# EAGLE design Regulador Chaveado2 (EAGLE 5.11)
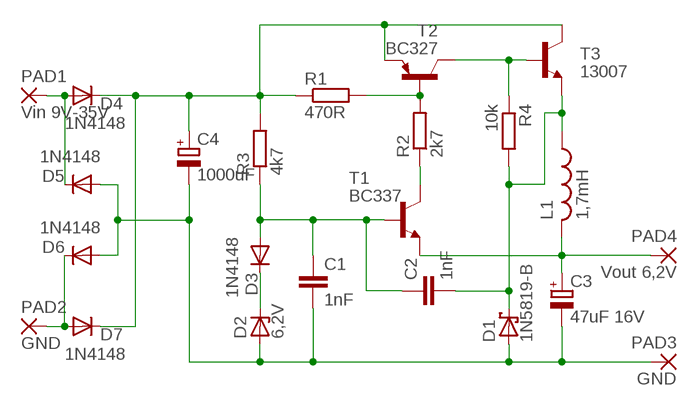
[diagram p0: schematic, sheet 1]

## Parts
C1  1nF  C-EU050-025X075  [C050-025X075]
C2  1nF  C-EU050-025X075  [C050-025X075]
C3  47uF 16V  CPOL-EUE2.5-5  [E2,5-5]
C4  1000uF  CPOL-EUE7.5-16  [E7,5-16]
D1  1N5819-B  [DO41-7.6]
D2  6,2V  ZPY  [DO41Z10]
D3  1N4148  1N4148DO35-7  [DO35-7]
D4  1N4148  1N4148DO35-7  [DO35-7]
D5  1N4148  1N4148DO35-7  [DO35-7]
D6  1N4148  1N4148DO35-7  [DO35-7]
D7  1N4148  1N4148DO35-7  [DO35-7]
L1  1,7mH  L-USL-TRAFO  [TRAFO16MM]
PAD1  Vin 9V-35V  2,54/1,0  [2,54/1,0]
PAD2  GND  2,54/1,0  [2,54/1,0]
PAD3  GND  2,54/1,0  [2,54/1,0]
PAD4  Vout 6,2V  2,54/1,0  [2,54/1,0]
R1  470R  R-EU_0207/10  [0207/10]
R2  2k7  R-EU_0207/10  [0207/10]
R3  4k7  R-EU_0207/10  [0207/10]
R4  10k  R-EU_0207/10  [0207/10]
T1  BC337  BC337-16-NPN-TO92-CBE  [TO92-CBE]
T2  BC327  MPSA63-PNP-TO92-CBE  [TO92-CBE]
T3  13007  -NPN-TO220V  [TO220V]

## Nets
N$1: C1.2 C3.- C4.- D1.A D2.A D5.A D6.A PAD3.1(P)
N$2: C3.+ L1.P$7 PAD4.1(P) T1.E
N$3: C4.+ D4.C D7.C R1.1 R3.2 T2.E T3.2(C)
N$4: D2.C D3.C
N$5: C1.1 C2.1 D3.A R3.1 T1.B
N$6: R4.1 T2.C T3.1(B)
N$7: R2.1 T1.C
N$8: D4.A D5.C PAD1.1(P)
N$9: R1.2 R2.2 T2.B
N$10: C2.2 D1.C L1.P$5 R4.2 T3.3(E)
N$11: D6.C D7.A PAD2.1(P)

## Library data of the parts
C1 C2 = resistor:C-EU: CAPACITOR, European symbol
C3 C4 = rcl:CPOL-EU: POLARIZED CAPACITOR, European symbol
D1 = diode:1N581*: 1.0A SCHOTTKY BARRIER RECTIFIER
D2 = diode:ZPY: Z DIODE
D3-D7 = diode:1N4148: DIODE
L1 = Inductors:L-US: INDUCTOR, American symbol
PAD1-PAD4 = wirepad:2,54/1,0: THROUGH-HOLE PAD
R1-R4 = resistor:R-EU_: RESISTOR, European symbol
T1 T3 = transistor:*-NPN-: NPN Transistror BF959 corrected 2008.03.06
T2 = transistor:*-PNP-: PNP Transistror

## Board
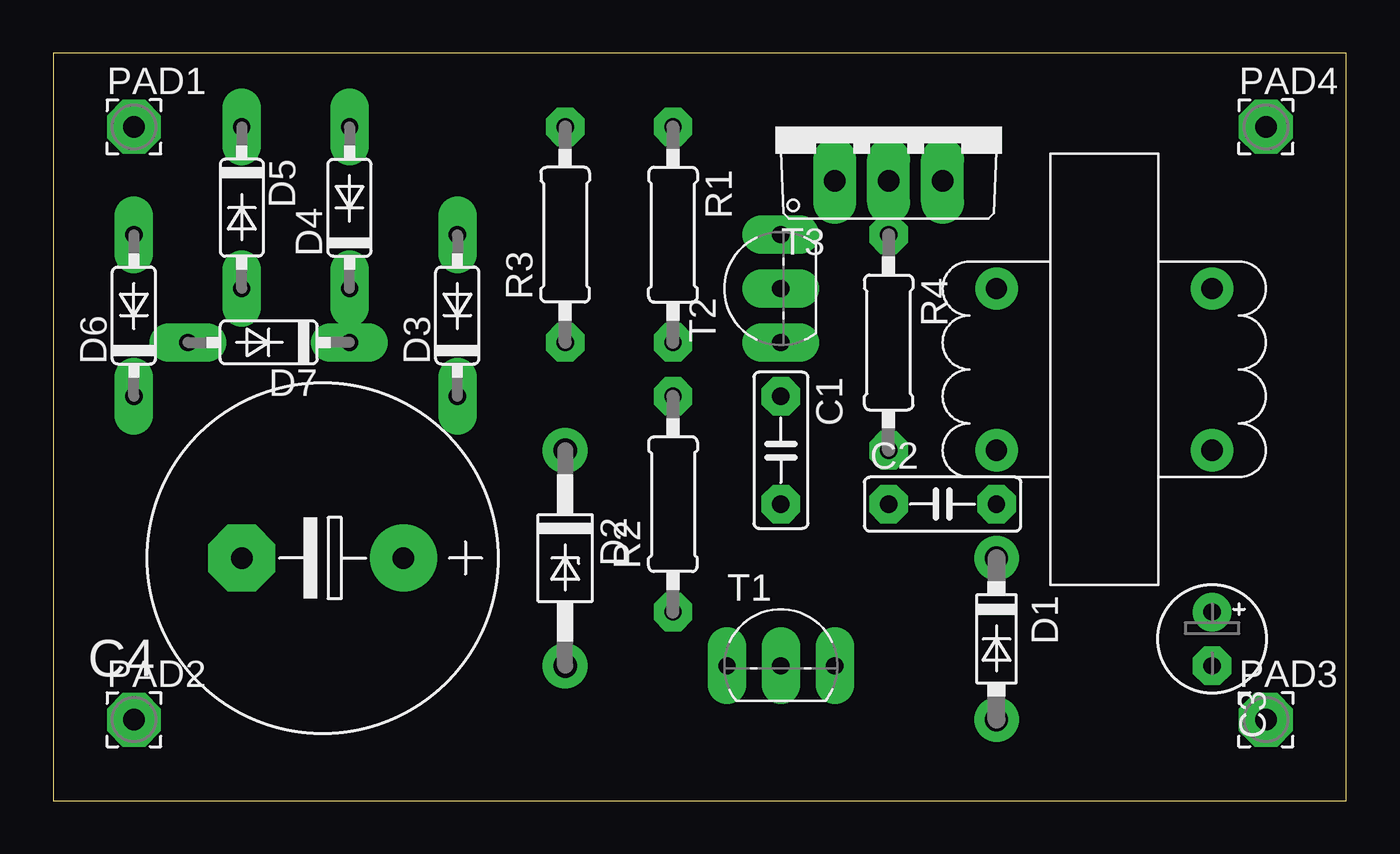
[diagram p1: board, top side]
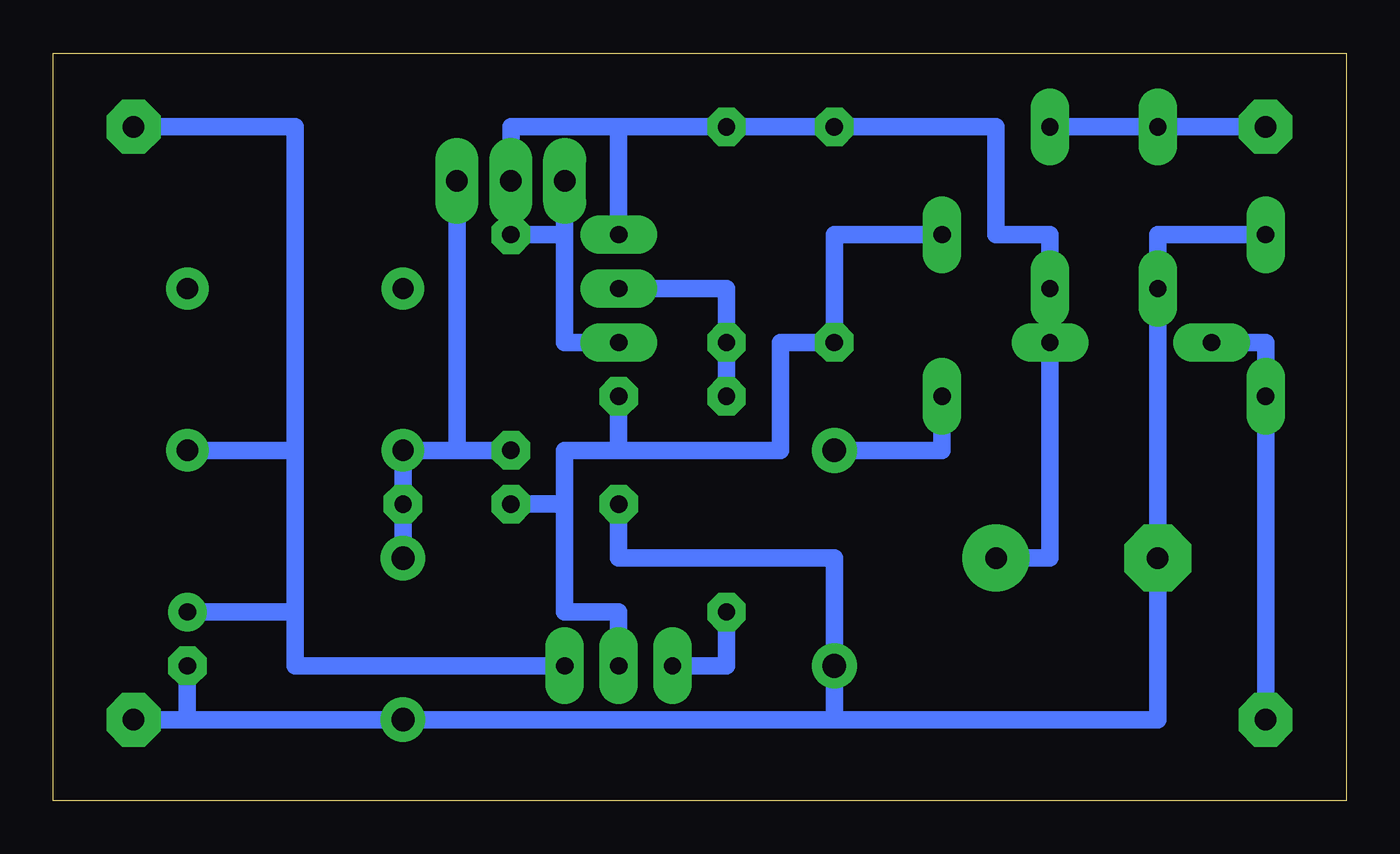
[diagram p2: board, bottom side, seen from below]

Size 60.94 x 35.23 mm. Coordinates in mm from the lower left corner, seen from the top.
Outline: 0,0 60.94,0 60.94,35.23 0,35.23 0,0
Copper layers (1*16): Top 0.035mm / dielectric 1.5mm / Bottom 0.035mm
Design rules "Manual": minimum track width 0.7mm, minimum drill 0.5mm, track to track 0.5mm, track to pad 0.5mm, pad to pad 0.5mm, via to via 1mm, smd to smd 8mil, copper to edge 40mil, drill to drill 1mm, minimum pad ring 0.5mm, minimum via ring 0.5mm, stop-mask expansion 4mil, vias tented up to drill 0mil, thermal gap 10mil

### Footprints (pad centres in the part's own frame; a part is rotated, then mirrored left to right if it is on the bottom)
C050-025X075 = drill 0.813 octagon: 1 -2.54,0; 2 2.54,0
E2,5-5 = drill 0.813 pad 1.6 round: + -1.27,0 | drill 0.813 pad 1.6 octagon: - 1.27,0
E7,5-16 = drill 1.016 pad 3.15 round: + -3.81,0 | drill 1.016 pad 3.15 octagon: - 3.81,0
DO41-7.6 = drill 1.1 pad 1.7 round: A 3.81,0; C -3.81,0
DO41Z10 = drill 1.118 round: A 5.08,0; C -5.08,0
DO35-7 = drill 0.813 long: A 3.81,0; C -3.81,0
TRAFO16MM = drill 1 round: P$5 -3.81,5.08; P$6 3.81,5.08; P$7 -3.81,-5.08; P$8 3.81,-5.08
2,54/1,0 = drill 1.016 pad 2.54 octagon: 1 0,0
0207/10 = drill 0.813 octagon: 1 -5.08,0; 2 5.08,0
TO92-CBE = drill 0.813 long: B 0,0; C -2.54,0; E 2.54,0
TO220V = drill 1.016 long: 1 -2.54,-2.54; 2 0,-2.54; 3 2.54,-2.54

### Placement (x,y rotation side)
C1  34.29,16.51 270 top
C2  41.91,13.97 0 top
C3  54.61,7.62 270 top
C4  12.7,11.43 180 top
D1  44.45,7.62 270 top
D2  24.13,11.43 270 top
D3  19.05,22.86 90 top
D4  13.97,27.94 90 top
D5  8.89,27.94 270 top
D6  3.81,22.86 90 top
D7  10.16,21.59 180 top
L1  49.53,20.32 90 top
PAD1  3.81,31.75 0 top
PAD2  3.81,3.81 0 top
PAD3  57.15,3.81 0 top
PAD4  57.15,31.75 0 top
R1  29.21,26.67 270 top
R2  29.21,13.97 90 top
R3  24.13,26.67 90 top
R4  39.37,21.59 270 top
T1  34.29,6.35 0 top
T2  34.29,24.13 90 top
T3  39.37,31.75 0 top

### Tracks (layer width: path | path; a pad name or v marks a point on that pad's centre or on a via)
N$1
  Bottom 0.813: D6.A 8.89,26.67 D5.A C4.- 8.89,3.81 24.13,3.81 | 24.13,3.81 D1.A 54.61,3.81 | 54.61,3.81 PAD3.1 | 54.61,3.81 C3.- | 24.13,3.81 D2.A 24.13,11.43 34.29,11.43 C1.2
N$2
  Bottom 0.813: 49.53,16.51 L1.P$7 | 49.53,8.89 49.53,6.35 T1.E | 49.53,8.89 49.53,16.51 | 49.53,8.89 C3.+ | PAD4.1 49.53,31.75 49.53,16.51
N$3
  Bottom 0.813: 34.29,31.75 R1.1 R3.2 16.51,31.75 16.51,26.67 13.97,26.67 D4.C D7.C 13.97,11.43 C4.+ | 34.29,31.75 39.37,31.75 T3.2 | 34.29,31.75 T2.E
N$4
  Bottom 0.813: D3.C 19.05,16.51 D2.C
N$5
  Bottom 0.813: 34.29,16.51 36.83,16.51 36.83,13.97 | 34.29,16.51 26.67,16.51 26.67,21.59 R3.1 24.13,26.67 D3.A | 36.83,13.97 36.83,8.89 34.29,8.89 T1.B | 36.83,13.97 C2.1 | 34.29,16.51 C1.1
N$6
  Bottom 0.813: 36.83,26.67 36.83,21.59 T2.C | 36.83,26.67 T3.1 | 36.83,26.67 R4.1
N$7
  Bottom 0.813: R2.1 29.21,6.35 T1.C
N$8
  Bottom 0.813: PAD1.1 D5.C D4.A
N$9
  Bottom 0.813: R2.2 R1.2 29.21,24.13 T2.B
N$10
  Bottom 0.813: D1.C C2.2 L1.P$5 41.91,16.51 | R4.2 41.91,16.51 | 41.91,16.51 T3.3
N$11
  Bottom 0.813: PAD2.1 D6.C 3.81,21.59 D7.A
